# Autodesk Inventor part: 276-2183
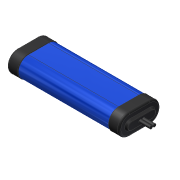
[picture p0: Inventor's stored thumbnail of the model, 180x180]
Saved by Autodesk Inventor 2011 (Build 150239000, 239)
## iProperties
Company: Autodesk Inc.
Created: 2010-06
Part Number: 276-2183
Document SubType Name: Modeling
Designer: Autodesk Inc.
Density: 1 g/cm^3
Catalog Web Link: http://www.vexrobotics.com/products/accessories/power/276-2183.html
Description: VEX 7.2V Ni-Cad Battery
Vendor: Innovation First, Inc.
Author: Autodesk Inc.
Title: VEX Robotics Kit of Parts
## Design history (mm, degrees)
sketch "Sketch1"
  geometry: L1 (-11.811, -11.684)-(11.811, -11.684); L2 (11.811, 11.684)-(-11.811, 11.684); A1 r 11.684 centre (11.811, 0) between (11.811, -11.684) and (11.811, 11.684); A2 r 11.684 centre (-11.811, 0) between (-11.811, 11.684) and (-11.811, -11.684); 2 further points
  constraints: 4 end point, 4 point on circle, 4 tangent, 2 centre point, 1 horizontal, 1 horizontal alignment, 1 midpoint, 1 parallel, 1 vertical alignment
  dimensions: "d0" = 23.622 distance of L2.start L2.end; "d1" = 11.684 radius of A1
extrude "Extrusion1" new body sketch "Sketch1" stored distance "d2" = 130.81; taper "d3" = 0 deg
sketch "Sketch2"
  geometry: L1 (11.811, -11.684)-(-11.811, -11.684) reference; L2 (-11.811, 11.684)-(11.811, 11.684) reference; L3 (-11.811, 12.192)-(11.811, 12.192); L4 (11.811, -12.192)-(-11.811, -12.192); A1 r 11.684 centre (-11.811, 0) between (-11.811, 11.684) and (-11.811, -11.684) reference; A2 r 11.684 centre (11.811, 0) between (11.811, -11.684) and (11.811, 11.684) reference; A3 r 12.192 centre (-11.811, 0) between (-11.811, 12.192) and (-11.811, -12.192); A4 r 12.192 centre (11.811, 0) between (11.811, -12.192) and (11.811, 12.192); 1 further point
  constraints: 4 end point, 4 point on circle, 2 centre point, 3 other
  dimensions: "d4" = 0.508 distance between parallel lines of L4 L1
extrude "Extrusion2" join sketch "Sketch2" distance "d5" = 12.954; taper "d6" = 0 deg
sketch "Sketch3"
  geometry: L1 (11.811, -11.684)-(-11.811, -11.684) reference; L2 (-11.811, 11.684)-(11.811, 11.684) reference; L3 (11.811, -12.192)-(-11.811, -12.192); L4 (-11.811, 12.192)-(11.811, 12.192); A1 r 11.684 centre (-11.811, 0) between (-11.811, 11.684) and (-11.811, -11.684) reference; A2 r 11.684 centre (11.811, 0) between (11.811, -11.684) and (11.811, 11.684) reference; A3 r 12.192 centre (11.811, 0) between (11.811, -12.192) and (11.811, 12.192); A4 r 12.192 centre (-11.811, 0) between (-11.811, 12.192) and (-11.811, -12.192); 1 further point
  constraints: 4 end point, 4 point on circle, 2 centre point, 3 other
  dimensions: "d11" = 0.508 distance between parallel lines of L4 L2
extrude "Extrusion3" join sketch "Sketch3" distance "d12" = 12.954; taper "d13" = 0 deg
chamfer "Chamfer1" distance "d7" = 0.508; stored, may be unused: second distance "d8" = 3.175, angle "d9" = 45 deg
fillet "Fillet1" dims "d10" = 2.032
sketch "Sketch4"
  geometry: L1 (-11.811, 10.16)-(11.811, 10.16) reference; L2 (11.811, -10.16)-(-11.811, -10.16) reference; L3 (-11.811, 5.842)-(11.811, 5.842); L4 (11.811, -5.842)-(-11.811, -5.842); A1 r 10.16 centre (-11.811, 0) between (-11.811, 10.16) and (-11.811, -10.16) reference; A2 r 10.16 centre (11.811, 0) between (11.811, -10.16) and (11.811, 10.16) reference; A3 r 5.842 centre (-11.811, 0) between (-11.811, 5.842) and (-11.811, -5.842); A4 r 5.842 centre (11.811, 0) between (11.811, -5.842) and (11.811, 5.842); 1 further point
  constraints: 4 end point, 4 point on circle, 2 centre point, 3 other
  dimensions: "d14" = 4.318 distance between parallel lines of L2 L4
extrude "Extrusion4" join sketch "Sketch4" distance "d15" = 2.54; taper "d16" = -30 deg
fillet "Fillet2" dims "d17" = 0.508
sketch "Sketch5"
  geometry: C1 r 1.778 at (-1.905, 0); C2 r 1.778 at (1.905, 0); 1 further point
  constraints: 2 centre point, 2 horizontal alignment, 1 equal radius
  dimensions: "d18" = 3.556 diameter of C2; "d19" = 3.81 distance of C1.centre C2.centre; "d20" = 1.905 distance of C2.centre point (0, 0) (= 0.5 x d19)
extrude "Extrusion5" join sketch "Sketch5" distance "d21" = 12.7; taper "d22" = 0 deg
body "Solid1"
